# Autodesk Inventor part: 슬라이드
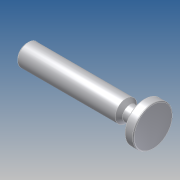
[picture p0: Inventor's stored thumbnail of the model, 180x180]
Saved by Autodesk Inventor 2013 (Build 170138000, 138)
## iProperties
Company: 한국ATC센터
Created: 2014-02
Part Number: 슬라이드
Document SubType Name: Modeling
Designer: KYOUNG IL JANG
Density: 7.86 g/cm^3
Mass: 68.0563 g
Surface Area: 34.7349 cm^2
Volume: 8.65856 cm^3
Material: 강, 연강
Vendor: CBT Solutions
Author: KYOUNG IL JANG
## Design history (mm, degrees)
sketch "스케치1"
  geometry: L1 (-35, 0)-(35, 0); L2 (35, 0)-(35, 11); L3 (35, 11)-(30, 11); L4 (30, 11)-(30, 4); L5 (30, 4)-(22, 4); L6 (22, 4)-(20, 6); L7 (20, 6)-(-35, 6); L8 (-35, 6)-(-35, 0); 1 further point
  constraints: 16 end point, 4 parallel, 2 midpoint, 2 perpendicular, 1 horizontal
  dimensions: "d0" = 70 distance of L1.start L1.end; "d1" = 12 diameter of L7 L1; "d2" = 22 diameter of L3 L1; "d3" = 5 distance of L2.end L3.end; "d4" = 8 diameter of L5 L1; "d5" = 135 deg angle of L6 L5; "d6" = 15 distance from line of L2 L6.end
revolve "회전1" sketch "스케치1" stored, may be unused: angle "d7" = 90 deg
chamfer "모따기1" distance "d8" = 1; stored, may be unused: second distance "d9" = 2, angle "d10" = 45 deg
fillet "모깎기1" dims "d11" = 0.5
node "솔리드1"
